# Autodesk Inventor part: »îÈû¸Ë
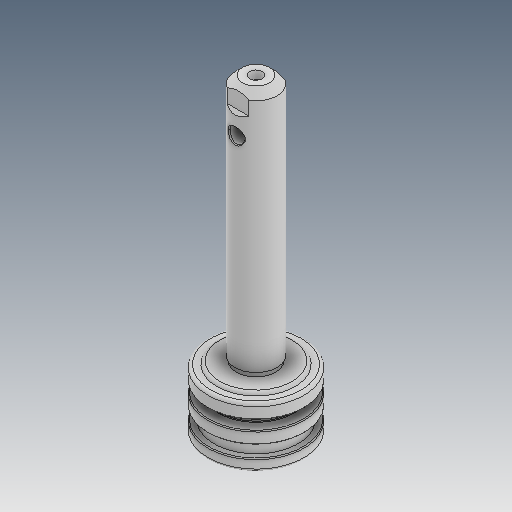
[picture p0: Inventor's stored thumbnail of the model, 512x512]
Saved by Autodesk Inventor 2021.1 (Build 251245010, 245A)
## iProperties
Created: 2013-04
Part Number: »îÈû¸Ë
Material: Ogólny
Document SubType Name: Modeling
Designer: user
Density: 1 g/cm^3
Appearance: Domyślna
Author: user
Revision Number: ÈÎºÎ
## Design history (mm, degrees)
feature "µ¹½Ç1"
node "Bryła1"
